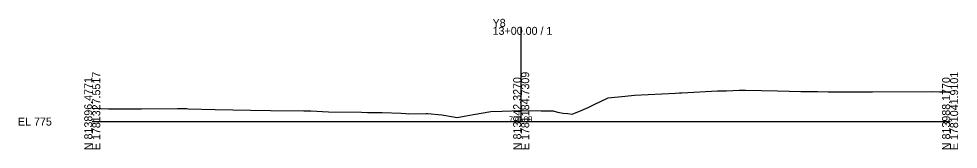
# Model space of a CAD drawing. Extents: x -26 to 303, y -10 to 5036.
# Drawn here: x -25.7 to 302.8, y 4990.3 to 5036.1 of the extents above; entities that cross this region are included whole.
import ezdxf

# ---------------------------------------------------------------- set-up
doc = ezdxf.new("R2010")
doc.units = 0
for name, color, linetype in [('Exist Cross Section Cell', 7, 'Continuous'), ('Exist XS Center Line Elevation Label', 7, 'Continuous'), ('Exist XS Ground Line', 7, 'Continuous')]:
    doc.layers.add(name, color=color, linetype=linetype)

msp = doc.modelspace()

# ---------------------------------------------------------------- linework, layer by layer
at = {"layer": 'Exist Cross Section Cell'}
for p, q in [((150, 5000), (150, 5033.23)), ((0, 5000), (150, 5000)), ((150, 5000), (300, 5000))]:
    msp.add_line(p, q, dxfattribs=at)
at = {"layer": 'Exist XS Ground Line'}
for p, q in [((205.35, 5010.11), (206.14, 5010.14)), ((206.14, 5010.14), (218.65, 5010.77)), ((218.65, 5010.77), (221.86, 5010.84)), ((221.86, 5010.84), (226.25, 5011.01)), ((226.25, 5011.01), (227.45, 5011.08)), ((227.45, 5011.08), (228.41, 5011.06)), ((228.41, 5011.06), (239.69, 5010.74)), ((239.69, 5010.74), (247.77, 5010.53)), ((247.77, 5010.53), (253.6, 5010.52)), ((253.6, 5010.52), (257.39, 5010.49)), ((257.39, 5010.49), (263.99, 5010.43)), ((263.99, 5010.43), (272.87, 5010.46)), ((272.87, 5010.46), (293.52, 5010.52)), ((293.52, 5010.52), (296.29, 5010.49)), ((296.29, 5010.49), (298.65, 5010.43)), ((298.65, 5010.43), (300, 5010.39)), ((175.24, 5005.88), (180.47, 5008.29)), ((180.47, 5008.29), (186.4, 5008.96)), ((186.4, 5008.96), (189.59, 5009.3)), ((189.59, 5009.3), (204, 5010.02)), ((204, 5010.02), (205.35, 5010.11)), ((0, 5004.71), (3.01, 5004.56)), ((3.01, 5004.56), (5.73, 5004.47)), ((5.73, 5004.47), (12.87, 5004.49)), ((12.87, 5004.49), (17.21, 5004.48)), ((17.21, 5004.48), (29.84, 5004.55)), ((29.84, 5004.55), (32.61, 5004.57)), ((32.61, 5004.57), (33.13, 5004.55)), ((33.13, 5004.55), (33.5, 5004.54)), ((33.5, 5004.54), (42.97, 5004.3)), ((42.97, 5004.3), (55.39, 5004.05)), ((55.39, 5004.05), (62.37, 5003.91)), ((62.37, 5003.91), (74.05, 5003.81)), ((74.05, 5003.81), (76.44, 5003.76)), ((76.44, 5003.76), (82.6, 5003.42)), ((133.38, 5002.45), (139.37, 5003.56)), ((139.37, 5003.56), (143.36, 5003.68)), ((143.36, 5003.68), (150, 5003.89)), ((150, 5003.89), (150.31, 5003.9)), ((150.31, 5003.9), (156.94, 5003.82)), ((156.94, 5003.82), (161.14, 5003.74)), ((161.14, 5003.74), (162.73, 5003.37)), ((167.84, 5002.61), (170.95, 5003.89)), ((170.95, 5003.89), (173.43, 5004.99)), ((173.43, 5004.99), (175.24, 5005.88)), ((82.6, 5003.42), (94.16, 5003.26)), ((94.16, 5003.26), (96.22, 5003.21)), ((96.22, 5003.21), (101.39, 5003.16)), ((101.39, 5003.16), (108.01, 5002.93)), ((108.01, 5002.93), (109.66, 5002.82)), ((109.66, 5002.82), (110.67, 5002.78)), ((110.67, 5002.78), (116.76, 5002.89)), ((116.76, 5002.89), (117.24, 5002.89)), ((117.24, 5002.89), (122.29, 5002.36)), ((122.29, 5002.36), (126.32, 5001.69)), ((126.32, 5001.69), (127.54, 5001.49)), ((127.54, 5001.49), (130.76, 5001.98)), ((130.76, 5001.98), (132.06, 5002.21)), ((132.06, 5002.21), (133.38, 5002.45)), ((162.73, 5003.37), (164.7, 5002.92)), ((164.7, 5002.92), (166.27, 5002.79)), ((166.27, 5002.79), (167.84, 5002.61))]:
    msp.add_line(p, q, dxfattribs=at)

# ---------------------------------------------------------------- texts
at = {"layer": 'Exist Cross Section Cell'}
for s, p in [('Y8', (140, 5033.23)), ('13+00.00 / 1', (140, 5030.43)), ('EL 775', (-26, 4998.6))]:
    msp.add_text(s, height=2.8, dxfattribs=at).set_placement(p)
for s, p in [('E 1781327.5517', (2.8, 4990)), ('E 1781184.7309', (152.8, 4990)), ('E 1781041.9101', (302.8, 4990)), ('N 813896.4771', (0, 4990)), ('N 813942.3270', (150, 4990)), ('N 813988.1770', (300, 4990))]:
    msp.add_text(s, height=2.8, rotation=90, dxfattribs=at).set_placement(p)
at = {"layer": 'Exist XS Center Line Elevation Label'}
msp.add_text('778.89', height=2, dxfattribs=at).set_placement((145.73, 4999.89))

doc.saveas('drawing.dxf')
